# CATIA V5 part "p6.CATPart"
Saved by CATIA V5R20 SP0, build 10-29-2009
Part number: p6
Publications: "Line.1", "Line.2", "Line.3", "Plane.1", "Plane.2", "Line.4"
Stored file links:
  D:\Dropbox\IAO_2011\MMS_GR2\IAO_2011_1439_jlicbarski\p6.CATPart
  D:\Dropbox\IAO_2011\MMS_GR2\IAO_2011_1439_jlicbarski\train.CATProduct

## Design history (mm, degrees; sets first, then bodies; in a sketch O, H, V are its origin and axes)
AxisSystem1: origin (0, 0, 0), X (1, 0, 0), Y (0, 1, 0), Z (0, 0, 1)
Set1
  Point1: linked copy from another document
  Point2: linked copy from another document
Body1 (main body)
  Line1: type PtPt, FirstPoint Point1, SecondPoint Point2
  Line2: type PtDir, RefPoint Point2, Direction edge [XY plane of AxisSystem1 | ZX plane of AxisSystem1], Start 0, End 10
  Line3: type PtDir, RefPoint Point1, Direction edge [XY plane of AxisSystem1 | ZX plane of AxisSystem1], Start 0, End 10
  Plane1: type Normal, Curve Line2
  Line4: type PtDir, RefPoint Point1, Direction edge [XY plane of AxisSystem1 | ZX plane of AxisSystem1], Start 0, End -20
  Plane2: type Normal, Curve Line4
